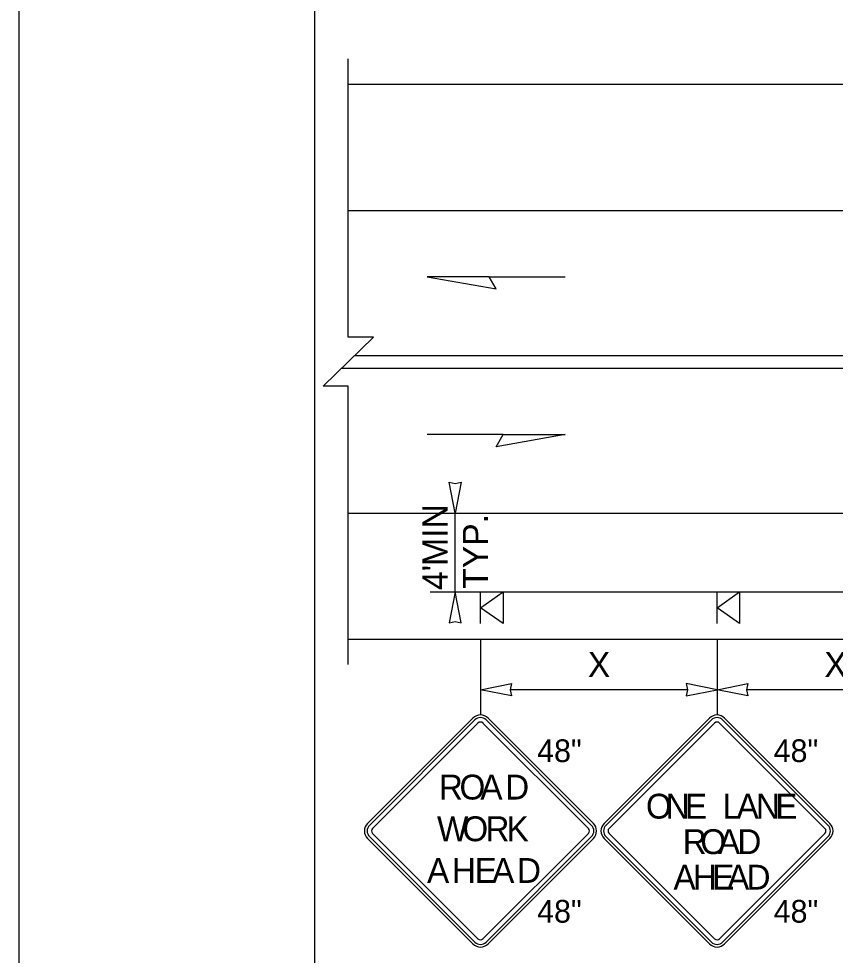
# Model space of a CAD drawing. Extents: x 99999.1 to 100095.7, y 99995 to 100010.7.
# Drawn here: x 99999.062 to 100001.652, y 100004.73 to 100007.7 of the extents above; entities that cross this region are included whole.
import ezdxf

# ---------------------------------------------------------------- set-up
doc = ezdxf.new("R2010")
doc.units = 0
for name, color, linetype in [('RD_ED_ShoulderPavedEdge', 7, 'Continuous'), ('RD_MK_LineDblYellowCenter', 7, 'Continuous'), ('RD_MK_LineEdgeWhite', 7, 'Continuous'), ('SH_GI_PlotLimits', 7, 'Continuous'), ('SH_GI_SheetBorder', 7, 'Continuous'), ('TR_SN_ConstructionSigns', 7, 'Continuous'), ('TR_WZ_PortableSignMountBlk-Org', 7, 'Continuous'), ('TR_WZ_WorkZoneDetails', 7, 'Continuous'), ('TR_WZ_WorkZoneTextCurrent', 7, 'Continuous')]:
    doc.layers.add(name, color=color, linetype=linetype)

msp = doc.modelspace()

# ---------------------------------------------------------------- linework, layer by layer
at = {"layer": 'RD_ED_ShoulderPavedEdge'}
for p, q in [((100000.1076, 100007.4923), (100015.6424, 100007.4923)), ((100000.1076, 100005.7323), (100015.6424, 100005.7323))]:
    msp.add_line(p, q, dxfattribs=at)
at = {"layer": 'RD_MK_LineDblYellowCenter'}
for p, q in [((100000.1282, 100006.6323), (100003.4767, 100006.6323)), ((100000.0869, 100006.5923), (100003.4767, 100006.5923))]:
    msp.add_line(p, q, dxfattribs=at)
at = {"layer": 'RD_MK_LineEdgeWhite'}
for p, q in [((100000.1076, 100007.0923), (100015.6424, 100007.0923)), ((100000.1076, 100006.1323), (100015.6424, 100006.1323))]:
    msp.add_line(p, q, dxfattribs=at)
at = {"layer": 'SH_GI_PlotLimits'}
msp.add_lwpolyline([(99999.0625, 99999.6875), (100016.0625, 99999.6875), (100016.0625, 100010.6875), (99999.0625, 100010.6875)], close=True, dxfattribs=at)
at = {"layer": 'SH_GI_SheetBorder'}
msp.add_line((100000, 100010.375), (100000, 100000), dxfattribs=at)
at = {"layer": 'TR_SN_ConstructionSigns'}
for p, q in [((100000.5028, 100005.4824), (100000.1687, 100005.1483)), ((100000.5088, 100005.4765), (100000.1746, 100005.1424)), ((100000.8787, 100005.1424), (100000.5445, 100005.4765)), ((100000.8846, 100005.1483), (100000.5505, 100005.4824)), ((100001.2528, 100005.4824), (100000.9187, 100005.1483)), ((100001.2588, 100005.4765), (100000.9246, 100005.1424)), ((100001.6287, 100005.1424), (100001.2945, 100005.4765)), ((100001.6346, 100005.1483), (100001.3005, 100005.4824)), ((100000.1846, 100005.1324), (100000.5187, 100005.4665)), ((100000.5346, 100005.4665), (100000.8687, 100005.1324)), ((100000.9346, 100005.1324), (100001.2687, 100005.4665)), ((100001.2846, 100005.4665), (100001.6187, 100005.1324)), ((100000.5187, 100004.7824), (100000.1846, 100005.1165)), ((100000.8687, 100005.1165), (100000.5346, 100004.7824)), ((100001.2687, 100004.7824), (100000.9346, 100005.1165)), ((100001.6187, 100005.1165), (100001.2846, 100004.7824)), ((100000.1687, 100005.1006), (100000.5028, 100004.7665)), ((100000.1746, 100005.1066), (100000.5088, 100004.7725)), ((100000.5445, 100004.7725), (100000.8787, 100005.1066)), ((100000.5505, 100004.7665), (100000.8846, 100005.1006)), ((100000.9187, 100005.1006), (100001.2528, 100004.7665)), ((100000.9246, 100005.1066), (100001.2588, 100004.7725)), ((100001.2945, 100004.7725), (100001.6287, 100005.1066)), ((100001.3005, 100004.7665), (100001.6346, 100005.1006))]:
    msp.add_line(p, q, dxfattribs=at)
for centre, radius, start, end in [((100000.5267, 100005.4586), 0.0338, 45, 135), ((100000.5267, 100005.4586), 0.0253, 45, 135), ((100001.2767, 100005.4586), 0.0338, 45, 135), ((100001.2767, 100005.4586), 0.0253, 45, 135), ((100000.5267, 100005.4586), 0.0113, 45, 135), ((100001.2767, 100005.4586), 0.0113, 45, 135), ((100000.1925, 100005.1245), 0.0338, 135, 225), ((100000.8608, 100005.1245), 0.0338, 315, 45), ((100000.9425, 100005.1245), 0.0338, 135, 225), ((100001.6108, 100005.1245), 0.0338, 315, 45), ((100000.1925, 100005.1245), 0.0253, 135, 225), ((100000.1925, 100005.1245), 0.0113, 135, 225), ((100000.8608, 100005.1245), 0.0113, 315, 45), ((100000.8608, 100005.1245), 0.0253, 315, 45), ((100000.9425, 100005.1245), 0.0253, 135, 225), ((100000.9425, 100005.1245), 0.0113, 135, 225), ((100001.6108, 100005.1245), 0.0113, 315, 45), ((100001.6108, 100005.1245), 0.0253, 315, 45), ((100000.5267, 100004.7904), 0.0338, 225, 315), ((100000.5267, 100004.7904), 0.0253, 225, 315), ((100000.5267, 100004.7904), 0.0113, 225, 315), ((100001.2767, 100004.7904), 0.0338, 225, 315), ((100001.2767, 100004.7904), 0.0253, 225, 315), ((100001.2767, 100004.7904), 0.0113, 225, 315)]:
    msp.add_arc(centre, radius, start, end, dxfattribs=at)
at = {"layer": 'TR_WZ_PortableSignMountBlk-Org'}
for p, q in [((100000.5267, 100005.7824), (100000.5267, 100005.8824)), ((100001.2767, 100005.7824), (100001.2767, 100005.8824))]:
    msp.add_line(p, q, dxfattribs=at)
for points in [[(100000.5267, 100005.8323), (100000.5985, 100005.8824), (100000.5985, 100005.7824)], [(100001.2767, 100005.8323), (100001.3485, 100005.8824), (100001.3485, 100005.7824)]]:
    msp.add_lwpolyline(points, close=True, dxfattribs=at)
at = {"layer": 'TR_WZ_WorkZoneDetails'}
for p, q in [((100000.5541, 100006.8816), (100000.7952, 100006.8816)), ((100000.5987, 100006.3816), (100000.3576, 100006.3816)), ((100000.3667, 100006.1323), (100000.5267, 100006.1323)), ((100000.4467, 100005.8824), (100000.4467, 100006.1323)), ((100000.3667, 100005.8824), (100000.5267, 100005.8824)), ((100000.5267, 100005.8824), (100003.5267, 100005.8824)), ((100000.5267, 100005.7326), (100000.5267, 100005.4923)), ((100001.2767, 100005.7323), (100001.2767, 100005.4923)), ((100001.1829, 100005.5723), (100000.6204, 100005.5723)), ((100001.9329, 100005.5723), (100001.3704, 100005.5723))]:
    msp.add_line(p, q, dxfattribs=at)
msp.add_lwpolyline([(100000.1076, 100005.6523), (100000.1076, 100006.5349), (100000.0275, 100006.5349), (100000.1876, 100006.6898), (100000.1076, 100006.6898), (100000.1076, 100007.5723)], dxfattribs=at)
for points in [[(100000.3576, 100006.8816), (100000.5764, 100006.843), (100000.5541, 100006.8816)], [(100000.7952, 100006.3816), (100000.5764, 100006.343), (100000.5987, 100006.3816)], [(100000.4467, 100006.1323), (100000.4274, 100006.2306), (100000.4467, 100006.2261), (100000.4659, 100006.2306)], [(100000.4467, 100005.8824), (100000.4274, 100005.7841), (100000.4467, 100005.7887), (100000.4659, 100005.7841)], [(100000.5267, 100005.5723), (100000.6249, 100005.5916), (100000.6204, 100005.5723), (100000.6249, 100005.5531)], [(100001.2767, 100005.5723), (100001.1784, 100005.5916), (100001.1829, 100005.5723), (100001.1784, 100005.5531)], [(100001.2767, 100005.5723), (100001.3749, 100005.5916), (100001.3704, 100005.5723), (100001.3749, 100005.5531)]]:
    msp.add_lwpolyline(points, close=True, dxfattribs=at)

# ---------------------------------------------------------------- texts
at = {"layer": 'TR_SN_ConstructionSigns'}
for p in [(100000.7064, 100005.343), (100001.4564, 100005.343), (100000.7064, 100004.8339), (100001.4564, 100004.8339)]:
    msp.add_text('48"', height=0.072, rotation=360, dxfattribs=at).set_placement(p)
for s, height, p in [('R', 0.0788, (100000.3947, 100005.2243)), ('O', 0.0788, (100000.4601, 100005.2243)), ('A', 0.0788, (100000.5263, 100005.2243)), ('D', 0.0788, (100000.605, 100005.2243)), ('O', 0.0787, (100001.0514, 100005.1638)), ('N', 0.0787, (100001.1136, 100005.1638)), ('E', 0.0787, (100001.1751, 100005.1638)), ('L', 0.0787, (100001.294, 100005.1638)), ('A', 0.0787, (100001.3389, 100005.1638)), ('N', 0.0787, (100001.4003, 100005.1638)), ('E', 0.0787, (100001.4617, 100005.1638)), ('W', 0.0788, (100000.3888, 100005.0921)), ('O', 0.0788, (100000.4692, 100005.0921)), ('R', 0.0788, (100000.5424, 100005.0921)), ('K', 0.0788, (100000.6093, 100005.0921)), ('R', 0.0787, (100001.168, 100005.0513)), ('O', 0.0787, (100001.2239, 100005.0513)), ('A', 0.0787, (100001.2798, 100005.0513)), ('D', 0.0787, (100001.3412, 100005.0513)), ('A', 0.0788, (100000.3573, 100004.9599)), ('H', 0.0788, (100000.4361, 100004.9599)), ('E', 0.0788, (100000.5085, 100004.9599)), ('A', 0.0788, (100000.5637, 100004.9599)), ('D', 0.0788, (100000.6424, 100004.9599)), ('A', 0.0787, (100001.1388, 100004.9388)), ('H', 0.0787, (100001.2003, 100004.9388)), ('E', 0.0787, (100001.2617, 100004.9388)), ('A', 0.0787, (100001.3089, 100004.9388)), ('D', 0.0787, (100001.3704, 100004.9388))]:
    msp.add_text(s, height=height, dxfattribs=at).set_placement(p)
at = {"layer": 'TR_WZ_WorkZoneTextCurrent'}
for s, rotation, p in [('MIN', 90, (100000.4227, 100005.9648)), ('TYP.', 90, (100000.5507, 100005.892)), ("4'", 90, (100000.4227, 100005.8883)), ('X', 360, (100000.8669, 100005.6123)), ('X', 360, (100001.6169, 100005.6123))]:
    msp.add_text(s, height=0.08, rotation=rotation, dxfattribs=at).set_placement(p)

doc.saveas('drawing.dxf')
